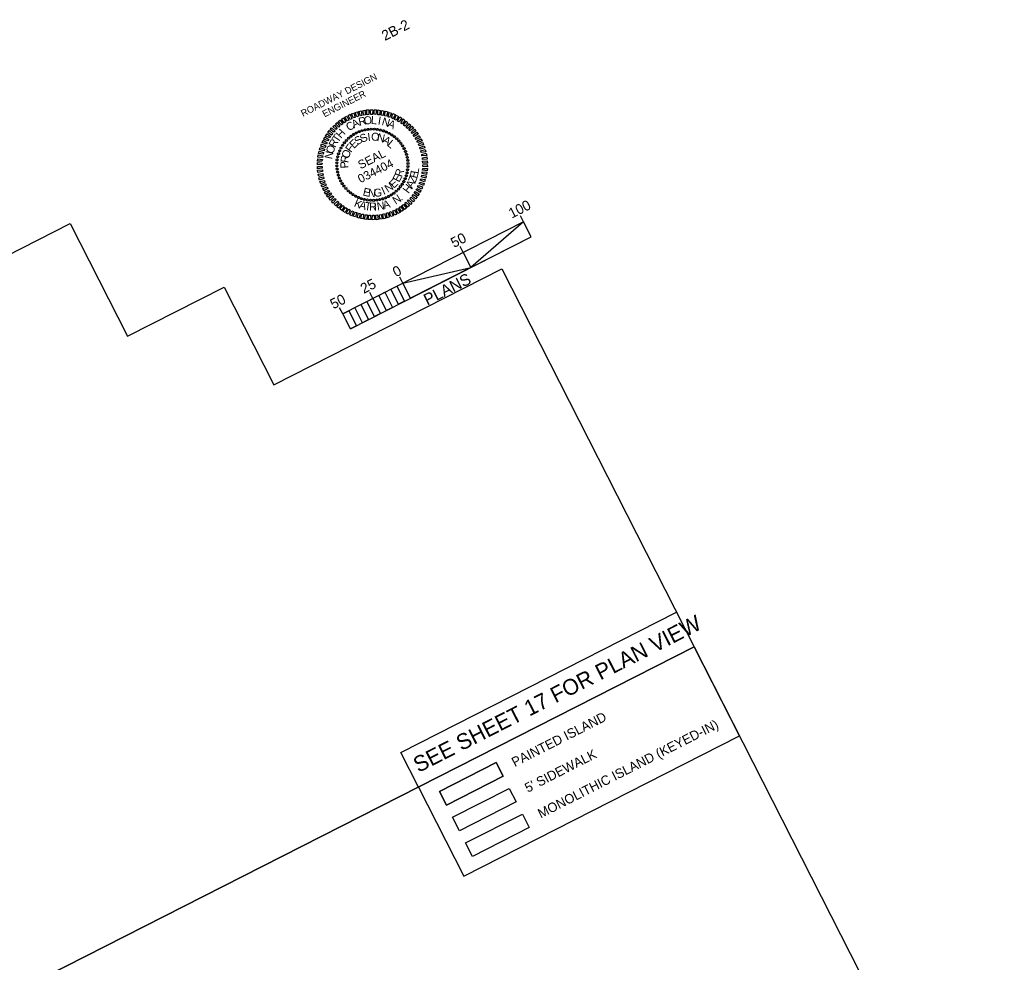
# Model space of a CAD drawing. Extents: x 2331355 to 2333079, y 611262 to 612828.
# Drawn here: x 2332342 to 2333079, y 612132 to 612828 of the extents above; entities that cross this region are included whole.
import ezdxf

# ---------------------------------------------------------------- set-up
doc = ezdxf.new("R2010")
doc.units = 0
for name, color, linetype in [('Default', 7, 'Continuous'), ('Prop Conc 4in Sidewalk', 7, 'Continuous'), ('Prop Conc 5in Monolithic Keyed In Island', 7, 'Continuous'), ('Prop Dimension Text', 7, 'Continuous'), ('Prop Lane Lines', 7, 'Continuous'), ('Sheet Data Field CELL', 7, 'Continuous'), ('Sheet Plan CELL', 7, 'Continuous'), ('Sheet Title CELL', 7, 'Continuous')]:
    doc.layers.add(name, color=color, linetype=linetype)

msp = doc.modelspace()

# ---------------------------------------------------------------- linework, layer by layer
at = {"layer": 'Default'}
msp.add_line((2332379.58, 612677.42), (2332421.89, 612594.18), dxfattribs=at)
for points in [[(2332623.93, 612286.52), (2332827.81, 612390.17), (2332840.79, 612364.62), (2332636.91, 612260.98)], [(2332670.41, 612195.11), (2332874.28, 612298.75), (2332840.79, 612364.62), (2332636.92, 612260.99)]]:
    msp.add_lwpolyline(points, close=True, dxfattribs=at)
at = {"layer": 'Prop Conc 4in Sidewalk'}
msp.add_lwpolyline([(2332662.16, 612238.7), (2332704.1, 612260.02), (2332709.22, 612249.95), (2332667.28, 612228.63)], close=True, dxfattribs=at)
at = {"layer": 'Prop Conc 5in Monolithic Keyed In Island'}
msp.add_lwpolyline([(2332671.81, 612219.72), (2332713.75, 612241.04), (2332718.87, 612230.97), (2332676.93, 612209.65)], close=True, dxfattribs=at)
at = {"layer": 'Prop Lane Lines'}
msp.add_lwpolyline([(2332652.51, 612257.69), (2332694.45, 612279), (2332699.57, 612268.93), (2332657.63, 612247.62)], close=True, dxfattribs=at)
msp.add_lwpolyline([(2332657.63, 612247.62), (2332699.57, 612268.93), (2332694.45, 612279), (2332652.51, 612257.69), (2332657.63, 612247.62)], dxfattribs=at)
at = {"layer": 'Sheet Data Field CELL'}
for p, q in [((2332587.13, 612741.95), (2332587.13, 612741.95)), ((2332588.97, 612743.29), (2332588.97, 612743.29)), ((2332590.99, 612744.42), (2332590.99, 612744.42)), ((2332593.1, 612745.36), (2332593.1, 612745.36)), ((2332595.26, 612746.09), (2332595.26, 612746.09)), ((2332597.43, 612746.71), (2332597.43, 612746.71)), ((2332599.72, 612747.09), (2332599.72, 612747.09)), ((2332602.02, 612747.24), (2332602.02, 612747.24)), ((2332604.32, 612747.27), (2332604.32, 612747.27)), ((2332606.6, 612747), (2332606.6, 612747)), ((2332608.89, 612746.61), (2332608.89, 612746.61)), ((2332611.06, 612745.98), (2332611.06, 612745.98)), ((2332613.26, 612745.19), (2332613.26, 612745.19)), ((2332615.28, 612744.18), (2332615.28, 612744.18)), ((2332617.28, 612742.99), (2332617.28, 612742.99)), ((2332619.17, 612741.67), (2332619.17, 612741.67)), ((2332580.86, 612735.3), (2332580.86, 612735.3)), ((2332582.17, 612737.19), (2332582.17, 612737.19)), ((2332583.63, 612738.91), (2332583.63, 612738.91)), ((2332585.28, 612740.5), (2332585.28, 612740.5)), ((2332620.89, 612740.21), (2332620.89, 612740.21)), ((2332622.48, 612738.56), (2332622.48, 612738.56)), ((2332623.94, 612736.72), (2332623.94, 612736.72)), ((2332625.27, 612734.87), (2332625.27, 612734.87)), ((2332577.23, 612726.9), (2332577.23, 612726.9)), ((2332577.86, 612729.08), (2332577.86, 612729.08)), ((2332578.65, 612731.28), (2332578.65, 612731.28)), ((2332579.66, 612733.3), (2332579.66, 612733.3)), ((2332626.4, 612732.86), (2332626.4, 612732.86)), ((2332627.34, 612730.74), (2332627.34, 612730.74)), ((2332628.08, 612728.58), (2332628.08, 612728.58)), ((2332628.69, 612726.41), (2332628.69, 612726.41)), ((2332576.57, 612722.34), (2332576.57, 612722.34)), ((2332576.6, 612720.04), (2332576.6, 612720.04)), ((2332576.84, 612724.62), (2332576.84, 612724.62)), ((2332629.07, 612724.12), (2332629.07, 612724.12)), ((2332629.22, 612721.82), (2332629.22, 612721.82)), ((2332629.26, 612719.52), (2332629.26, 612719.52)), ((2332576.75, 612717.74), (2332576.75, 612717.74)), ((2332577.13, 612715.45), (2332577.13, 612715.45)), ((2332577.75, 612713.28), (2332577.75, 612713.28)), ((2332627.96, 612712.78), (2332627.96, 612712.78)), ((2332628.59, 612714.95), (2332628.59, 612714.95)), ((2332628.98, 612717.24), (2332628.98, 612717.24)), ((2332578.48, 612711.12), (2332578.48, 612711.12)), ((2332579.42, 612709), (2332579.42, 612709)), ((2332580.55, 612706.99), (2332580.55, 612706.99)), ((2332581.89, 612705.14), (2332581.89, 612705.14)), ((2332623.65, 612704.67), (2332623.65, 612704.67)), ((2332624.97, 612706.56), (2332624.97, 612706.56)), ((2332626.16, 612708.56), (2332626.16, 612708.56)), ((2332627.17, 612710.58), (2332627.17, 612710.58)), ((2332583.34, 612703.3), (2332583.34, 612703.3)), ((2332584.93, 612701.65), (2332584.93, 612701.65)), ((2332586.65, 612700.19), (2332586.65, 612700.19)), ((2332588.54, 612698.87), (2332588.54, 612698.87)), ((2332590.54, 612697.68), (2332590.54, 612697.68)), ((2332614.84, 612697.44), (2332614.84, 612697.44)), ((2332616.85, 612698.57), (2332616.85, 612698.57)), ((2332618.7, 612699.9), (2332618.7, 612699.9)), ((2332620.54, 612701.36), (2332620.54, 612701.36)), ((2332622.19, 612702.95), (2332622.19, 612702.95)), ((2332592.56, 612696.67), (2332592.56, 612696.67)), ((2332594.76, 612695.88), (2332594.76, 612695.88)), ((2332596.94, 612695.25), (2332596.94, 612695.25)), ((2332599.22, 612694.86), (2332599.22, 612694.86)), ((2332601.51, 612694.58), (2332601.51, 612694.58)), ((2332603.8, 612694.62), (2332603.8, 612694.62)), ((2332606.1, 612694.77), (2332606.1, 612694.77)), ((2332608.39, 612695.15), (2332608.39, 612695.15)), ((2332610.56, 612695.77), (2332610.56, 612695.77)), ((2332612.72, 612696.5), (2332612.72, 612696.5)), ((2332670.09, 612656.11), (2332667.83, 612660.56)), ((2332603.24, 612622.11), (2332600.97, 612626.57)), ((2332580.95, 612610.79), (2332578.69, 612615.24))]:
    msp.add_line(p, q, dxfattribs=at)
for points in [[(2332584.32, 612753.29), (2332582.49, 612756.18), (2332584.04, 612756.95), (2332585.45, 612753.84)], [(2332586.57, 612754.43), (2332584.97, 612757.44), (2332586.52, 612758.2), (2332587.7, 612754.97)], [(2332588.96, 612755.52), (2332587.54, 612758.63), (2332589.22, 612759.16), (2332590.17, 612755.92)], [(2332591.38, 612756.33), (2332590.22, 612759.51), (2332591.87, 612760.09), (2332592.57, 612756.78)], [(2332594.01, 612757.07), (2332592.88, 612760.33), (2332594.65, 612760.79), (2332595.11, 612757.35)], [(2332596.56, 612757.65), (2332595.73, 612760.89), (2332597.41, 612761.19), (2332597.7, 612757.84)], [(2332599.09, 612757.92), (2332598.6, 612761.41), (2332600.2, 612761.54), (2332600.32, 612758.16)], [(2332601.64, 612758.15), (2332601.35, 612761.49), (2332603.13, 612761.61), (2332602.93, 612758.18)], [(2332604.34, 612758.21), (2332604.19, 612761.52), (2332605.99, 612761.47), (2332605.51, 612758.12)], [(2332606.81, 612757.92), (2332607, 612761.47), (2332608.72, 612761.13), (2332608.12, 612757.9)], [(2332609.45, 612757.54), (2332609.81, 612760.99), (2332611.55, 612760.61), (2332610.67, 612757.35)], [(2332611.97, 612757.03), (2332612.59, 612760.45), (2332614.29, 612759.93), (2332613.22, 612756.81)], [(2332614.5, 612756.3), (2332615.33, 612759.53), (2332617.04, 612759.01), (2332615.59, 612755.92)], [(2332617, 612755.49), (2332618.03, 612758.71), (2332619.67, 612757.97), (2332618.15, 612754.91)], [(2332619.35, 612754.42), (2332620.59, 612757.57), (2332622.19, 612756.69), (2332620.38, 612753.83)], [(2332621.57, 612753.16), (2332623.09, 612756.22), (2332624.71, 612755.3), (2332622.71, 612752.58)], [(2332576.19, 612746.9), (2332573.65, 612749.11), (2332574.86, 612750.29), (2332576.99, 612747.74)], [(2332578.09, 612748.68), (2332575.57, 612751.09), (2332576.97, 612752.25), (2332578.94, 612749.43)], [(2332580.05, 612750.37), (2332577.73, 612752.95), (2332579.19, 612753.9), (2332581.08, 612751.1)], [(2332582.12, 612751.83), (2332580.04, 612754.53), (2332581.52, 612755.55), (2332583.16, 612752.56)], [(2332623.85, 612751.76), (2332625.59, 612754.76), (2332626.95, 612753.64), (2332624.88, 612751.17)], [(2332625.84, 612750.26), (2332627.84, 612753.1), (2332629.22, 612751.93), (2332626.84, 612749.48)], [(2332627.83, 612748.52), (2332630.02, 612751.23), (2332631.29, 612750.06), (2332628.81, 612747.79)], [(2332629.75, 612746.69), (2332632.15, 612749.33), (2332633.24, 612747.95), (2332630.59, 612745.89)], [(2332569.96, 612738.49), (2332566.99, 612739.94), (2332567.73, 612741.46), (2332570.68, 612739.58)], [(2332571.38, 612740.73), (2332568.34, 612742.32), (2332569.38, 612743.82), (2332571.97, 612741.75)], [(2332572.79, 612742.9), (2332569.93, 612744.71), (2332571.02, 612746.12), (2332573.58, 612743.86)], [(2332574.31, 612744.95), (2332571.68, 612747), (2332572.77, 612748.3), (2332575.32, 612745.85)], [(2332631.49, 612744.76), (2332633.94, 612747.19), (2332635.05, 612745.76), (2332632.28, 612743.93)], [(2332633.08, 612742.76), (2332635.75, 612745), (2332636.73, 612743.5), (2332633.86, 612741.74)], [(2332634.54, 612740.68), (2332637.36, 612742.65), (2332638.29, 612741.12), (2332635.23, 612739.62)], [(2332567.17, 612731.31), (2332563.8, 612731.96), (2332564.4, 612733.64), (2332567.52, 612732.44)], [(2332567.84, 612733.74), (2332564.72, 612734.7), (2332565.24, 612736.4), (2332568.38, 612734.86)], [(2332568.94, 612736.16), (2332565.76, 612737.33), (2332566.5, 612738.97), (2332569.5, 612737.23)], [(2332635.82, 612738.39), (2332638.76, 612740.12), (2332639.59, 612738.55), (2332636.41, 612737.27)], [(2332637, 612736.04), (2332640.06, 612737.55), (2332640.78, 612735.97), (2332637.5, 612734.88)], [(2332637.95, 612733.7), (2332641.06, 612734.99), (2332641.71, 612733.32), (2332638.31, 612732.46)], [(2332566.03, 612726.19), (2332562.69, 612726.44), (2332562.86, 612728.25), (2332566.17, 612727.39)], [(2332566.49, 612728.69), (2332563.12, 612729.22), (2332563.5, 612730.96), (2332566.69, 612729.87)], [(2332638.83, 612731.14), (2332641.9, 612732.29), (2332642.41, 612730.54), (2332638.98, 612729.97)], [(2332639.41, 612728.59), (2332642.6, 612729.51), (2332643.09, 612727.81), (2332639.56, 612727.42)], [(2332639.9, 612726), (2332643.21, 612726.69), (2332643.37, 612724.93), (2332639.9, 612724.76)], [(2332565.57, 612721.01), (2332562.31, 612720.77), (2332562.25, 612722.58), (2332565.66, 612722.19)], [(2332565.77, 612718.39), (2332562.33, 612717.93), (2332562.27, 612719.74), (2332565.7, 612719.66)], [(2332565.62, 612723.6), (2332562.29, 612723.61), (2332562.53, 612725.4), (2332565.92, 612724.82)], [(2332640.05, 612723.47), (2332643.49, 612723.93), (2332643.56, 612722.12), (2332640.13, 612722.2)], [(2332640.25, 612720.84), (2332643.51, 612721.09), (2332643.58, 612719.28), (2332640.17, 612719.67)], [(2332565.93, 612715.86), (2332562.61, 612715.17), (2332562.45, 612716.93), (2332565.92, 612717.1)], [(2332566.41, 612713.27), (2332563.22, 612712.34), (2332562.73, 612714.04), (2332566.27, 612714.44)], [(2332566.99, 612710.72), (2332563.92, 612709.57), (2332563.41, 612711.32), (2332566.85, 612711.89)], [(2332639.34, 612713.17), (2332642.71, 612712.64), (2332642.33, 612710.9), (2332639.13, 612711.99)], [(2332639.79, 612715.67), (2332643.13, 612715.42), (2332642.96, 612713.61), (2332639.66, 612714.47)], [(2332640.2, 612718.26), (2332643.53, 612718.25), (2332643.29, 612716.46), (2332639.9, 612717.03)], [(2332567.87, 612708.16), (2332564.76, 612706.87), (2332564.11, 612708.54), (2332567.52, 612709.4)], [(2332568.82, 612705.81), (2332565.76, 612704.31), (2332565.04, 612705.89), (2332568.33, 612706.97)], [(2332570.01, 612703.47), (2332567.07, 612701.73), (2332566.23, 612703.31), (2332569.42, 612704.58)], [(2332636.89, 612705.7), (2332640.06, 612704.53), (2332639.33, 612702.89), (2332636.33, 612704.63)], [(2332637.98, 612708.12), (2332641.1, 612707.16), (2332640.58, 612705.46), (2332637.44, 612707)], [(2332638.65, 612710.55), (2332642.02, 612709.9), (2332641.43, 612708.22), (2332638.3, 612709.41)], [(2332571.28, 612701.18), (2332568.47, 612699.21), (2332567.54, 612700.74), (2332570.6, 612702.24)], [(2332572.74, 612699.1), (2332570.07, 612696.85), (2332569.1, 612698.36), (2332571.96, 612700.12)], [(2332574.34, 612697.1), (2332571.88, 612694.67), (2332570.77, 612696.1), (2332573.54, 612697.92)], [(2332631.51, 612696.9), (2332634.15, 612694.86), (2332633.05, 612693.56), (2332630.5, 612696.01)], [(2332633.04, 612698.96), (2332635.9, 612697.15), (2332634.81, 612695.74), (2332632.24, 612698)], [(2332634.44, 612701.13), (2332637.48, 612699.54), (2332636.44, 612698.03), (2332633.85, 612700.11)], [(2332635.86, 612703.37), (2332638.83, 612701.92), (2332638.1, 612700.4), (2332635.14, 612702.27)], [(2332576.07, 612695.17), (2332573.67, 612692.53), (2332572.58, 612693.91), (2332575.23, 612695.97)], [(2332577.99, 612693.34), (2332575.81, 612690.63), (2332574.54, 612691.8), (2332577.02, 612694.06)], [(2332579.99, 612691.6), (2332577.99, 612688.76), (2332576.6, 612689.92), (2332578.98, 612692.38)], [(2332581.97, 612690.1), (2332580.23, 612687.1), (2332578.87, 612688.22), (2332580.95, 612690.69)], [(2332623.7, 612690.03), (2332625.78, 612687.33), (2332624.31, 612686.31), (2332622.66, 612689.3)], [(2332625.78, 612691.49), (2332628.09, 612688.91), (2332626.64, 612687.96), (2332624.74, 612690.76)], [(2332627.73, 612693.18), (2332630.25, 612690.77), (2332628.85, 612689.61), (2332626.88, 612692.43)], [(2332629.64, 612694.96), (2332632.18, 612692.74), (2332630.96, 612691.56), (2332628.84, 612694.12)], [(2332584.26, 612688.7), (2332582.73, 612685.64), (2332581.12, 612686.56), (2332583.12, 612689.28)], [(2332586.47, 612687.44), (2332585.23, 612684.29), (2332583.64, 612685.16), (2332585.45, 612688.02)], [(2332588.82, 612686.37), (2332587.79, 612683.15), (2332586.16, 612683.89), (2332587.68, 612686.95)], [(2332591.33, 612685.56), (2332590.49, 612682.33), (2332588.79, 612682.85), (2332590.24, 612685.93)], [(2332593.86, 612684.82), (2332593.23, 612681.41), (2332591.53, 612681.93), (2332592.61, 612685.05)], [(2332596.38, 612684.32), (2332596.02, 612680.86), (2332594.27, 612681.24), (2332595.15, 612684.5)], [(2332599.02, 612683.94), (2332598.82, 612680.39), (2332597.1, 612680.73), (2332597.7, 612683.95)], [(2332601.49, 612683.65), (2332601.64, 612680.34), (2332599.83, 612680.39), (2332600.31, 612683.74)], [(2332604.19, 612683.71), (2332604.48, 612680.36), (2332602.7, 612680.25), (2332602.89, 612683.68)], [(2332606.74, 612683.94), (2332607.22, 612680.45), (2332605.63, 612680.32), (2332605.5, 612683.7)], [(2332609.27, 612684.21), (2332610.1, 612680.97), (2332608.41, 612680.67), (2332608.12, 612684.02)], [(2332611.81, 612684.79), (2332612.95, 612681.53), (2332611.17, 612681.06), (2332610.71, 612684.5)], [(2332614.44, 612685.53), (2332615.6, 612682.35), (2332613.95, 612681.77), (2332613.26, 612685.08)], [(2332616.87, 612686.34), (2332618.28, 612683.23), (2332616.6, 612682.7), (2332615.66, 612685.94)], [(2332619.26, 612687.43), (2332620.86, 612684.42), (2332619.3, 612683.65), (2332618.12, 612686.89)], [(2332621.51, 612688.57), (2332623.34, 612685.68), (2332621.78, 612684.91), (2332620.37, 612688.02)]]:
    msp.add_lwpolyline(points, close=True, dxfattribs=at)
for centre, major_axis in [((2332585.32, 612740.5), (-0.505, 0.562)), ((2332587.09, 612741.96), (-0.454, 0.604)), ((2332588.99, 612743.26), (-0.4, 0.641)), ((2332590.99, 612744.39), (-0.342, 0.673)), ((2332593.08, 612745.34), (-0.282, 0.701)), ((2332595.24, 612746.1), (-0.22, 0.723)), ((2332597.46, 612746.68), (-0.156, 0.739)), ((2332599.73, 612747.05), (-0.091, 0.75)), ((2332602.02, 612747.23), (-0.026, 0.755)), ((2332604.31, 612747.21), (0.04, 0.754)), ((2332606.6, 612746.99), (0.106, 0.748)), ((2332608.86, 612746.57), (0.171, 0.736)), ((2332611.07, 612745.95), (0.234, 0.718)), ((2332613.22, 612745.14), (0.296, 0.695)), ((2332615.29, 612744.15), (0.355, 0.667)), ((2332617.27, 612742.99), (0.412, 0.633)), ((2332619.13, 612741.65), (0.466, 0.595)), ((2332579.69, 612733.31), (-0.667, 0.355)), ((2332580.85, 612735.28), (-0.633, 0.412)), ((2332582.19, 612737.15), (-0.595, 0.466)), ((2332583.68, 612738.89), (-0.552, 0.516)), ((2332620.88, 612740.16), (0.516, 0.552)), ((2332622.49, 612738.52), (0.562, 0.505)), ((2332623.94, 612736.75), (0.604, 0.454)), ((2332625.24, 612734.85), (0.641, 0.4)), ((2332626.37, 612732.85), (0.673, 0.342)), ((2332577.27, 612726.87), (-0.736, 0.171)), ((2332577.89, 612729.08), (-0.718, 0.234)), ((2332578.7, 612731.23), (-0.695, 0.296)), ((2332627.32, 612730.76), (0.701, 0.282)), ((2332628.09, 612728.6), (0.723, 0.22)), ((2332628.66, 612726.38), (0.739, 0.156)), ((2332576.61, 612720.03), (-0.755, -0.026)), ((2332576.63, 612722.33), (-0.754, 0.04)), ((2332576.85, 612724.62), (-0.748, 0.106)), ((2332629.04, 612724.11), (0.75, 0.091)), ((2332629.19, 612719.53), (0.754, -0.04)), ((2332629.21, 612721.82), (0.755, 0.026)), ((2332576.79, 612717.75), (-0.75, -0.091)), ((2332577.17, 612715.48), (-0.739, -0.156)), ((2332577.74, 612713.26), (-0.723, -0.22)), ((2332578.5, 612711.09), (-0.701, -0.282)), ((2332627.93, 612712.77), (0.718, -0.234)), ((2332628.55, 612714.99), (0.736, -0.171)), ((2332628.97, 612717.24), (0.748, -0.106)), ((2332579.45, 612709), (-0.673, -0.342)), ((2332580.58, 612707), (-0.641, -0.4)), ((2332581.88, 612705.11), (-0.604, -0.454)), ((2332623.63, 612704.71), (0.595, -0.466)), ((2332624.97, 612706.58), (0.633, -0.412)), ((2332626.14, 612708.55), (0.667, -0.355)), ((2332627.13, 612710.62), (0.695, -0.296)), ((2332583.34, 612703.34), (-0.562, -0.505)), ((2332584.95, 612701.7), (-0.516, -0.552)), ((2332586.69, 612700.21), (-0.466, -0.595)), ((2332588.56, 612698.87), (-0.412, -0.633)), ((2332590.54, 612697.7), (-0.355, -0.667)), ((2332592.61, 612696.71), (-0.296, -0.695)), ((2332612.75, 612696.52), (0.282, -0.701)), ((2332614.84, 612697.47), (0.342, -0.673)), ((2332616.84, 612698.6), (0.4, -0.641)), ((2332618.73, 612699.9), (0.454, -0.604)), ((2332620.5, 612701.36), (0.505, -0.562)), ((2332622.14, 612702.96), (0.552, -0.516)), ((2332594.76, 612695.91), (-0.234, -0.718)), ((2332596.97, 612695.29), (-0.171, -0.736)), ((2332599.23, 612694.87), (-0.106, -0.748)), ((2332601.51, 612694.65), (-0.04, -0.754)), ((2332603.81, 612694.63), (0.026, -0.755)), ((2332606.09, 612694.81), (0.091, -0.75)), ((2332608.36, 612695.18), (0.156, -0.739)), ((2332610.58, 612695.76), (0.22, -0.723))]:
    msp.add_ellipse(centre, major_axis=major_axis, ratio=0.999708, dxfattribs=at)
at = {"layer": 'Sheet Plan CELL'}
for points in [[(2331354.84, 612198.14), (2332231.99, 612644.09), (2332248.84, 612610.95), (2332379.58, 612677.42), (2332421.89, 612594.18), (2332493.28, 612630.48), (2332529.96, 612558.33), (2332698.67, 612644.11), (2332840.79, 612364.62), (2331592.76, 611730.15)], [(2331592.76, 611730.15), (2332840.78, 612364.62), (2333078.69, 611896.65), (2331830.66, 611262.19)]]:
    msp.add_lwpolyline(points, close=True, dxfattribs=at)
at = {"layer": 'Sheet Title CELL'}
for p, q in [((2332714.65, 612678.76), (2332712.39, 612683.22)), ((2332714.65, 612678.76), (2332580.94, 612610.77)), ((2332586.61, 612599.63), (2332720.32, 612667.61)), ((2332670.08, 612656.1), (2332667.82, 612660.54)), ((2332670.08, 612656.1), (2332675.75, 612644.95)), ((2332625.52, 612633.42), (2332623.25, 612637.88)), ((2332603.23, 612622.09), (2332600.96, 612626.56)), ((2332612.14, 612626.64), (2332617.81, 612615.49)), ((2332580.94, 612610.77), (2332578.68, 612615.22)), ((2332578.68, 612615.22), (2332578.68, 612615.22))]:
    msp.add_line(p, q, dxfattribs=at)
for points in [[(2332714.65, 612678.76), (2332675.75, 612644.95), (2332720.32, 612667.61)], [(2332625.52, 612633.42), (2332675.75, 612644.95), (2332631.18, 612622.28)], [(2332616.6, 612628.9), (2332621.06, 612631.17), (2332626.73, 612620.02), (2332622.27, 612617.76)], [(2332607.69, 612624.36), (2332612.14, 612626.64), (2332617.81, 612615.49), (2332613.35, 612613.23)], [(2332589.86, 612615.31), (2332594.32, 612617.56), (2332599.99, 612606.42), (2332595.54, 612604.16)], [(2332598.78, 612619.83), (2332603.23, 612622.09), (2332608.89, 612610.96), (2332604.44, 612608.7)], [(2332580.94, 612610.77), (2332585.4, 612613.04), (2332591.07, 612601.9), (2332586.61, 612599.63)]]:
    msp.add_lwpolyline(points, close=True, dxfattribs=at)

# ---------------------------------------------------------------- texts
at = {"layer": 'Default'}
msp.add_text('SEE SHEET 17 FOR PLAN VIEW', height=11.6664, rotation=26.94752, dxfattribs=at).set_placement((2332636.97, 612271.34))
at = {"layer": 'Prop Dimension Text'}
for s, p in [('PAINTED ISLAND', (2332708.1, 612275.68)), ('MONOLITHIC ISLAND (KEYED-IN)', (2332727.4, 612237.71)), ("5' SIDEWALK", (2332717.75, 612256.7))]:
    msp.add_text(s, height=7, rotation=26.94653, dxfattribs=at).set_placement(p)
at = {"layer": 'Sheet Data Field CELL'}
for s, height, rotation, p in [('2B-2', 7.5, 26.94944, (2332612.19, 612812.36)), ('R', 5.92, 12.56828, (2332593.28, 612749.61)), ('O', 5.92, 5.36834, (2332596.75, 612750.56)), ('L', 5.92, 358.16806, (2332601.74, 612751.01)), ('I', 5.92, 350.96732, (2332606.67, 612750.78)), ('N', 5.92, 343.76609, (2332609.43, 612750.4)), ('C', 5.92, 34.16705, (2332585.77, 612745.51)), ('A', 5.92, 26.9675, (2332589.29, 612747.73)), ('A', 5.92, 336.56433, (2332613.61, 612749.12)), ('T', 5.92, 55.76695, (2332577.51, 612736.79)), ('H', 5.92, 48.56666, (2332579.71, 612739.92)), ('S', 5.92, 35.20279, (2332592.03, 612735.17)), ('S', 5.92, 25.84758, (2332595.34, 612736.99)), ('I', 5.92, 7.13678, (2332599.67, 612738.45)), ('O', 5.92, 357.78066, (2332601.87, 612738.79)), ('N', 5.92, 348.42379, (2332605.96, 612738.58)), ('A', 5.92, 329.70745, (2332609.88, 612737.57)), ('O', 5.92, 70.16892, (2332573.77, 612728.51)), ('R', 5.92, 62.96769, (2332575.44, 612733.08)), ('F', 5.91, 53.91421, (2332587.12, 612729.54)), ('E', 5.92, 44.55825, (2332589.35, 612732.5)), ('L', 5.92, 320.34803, (2332613.38, 612735.33)), ('N', 5.92, 77.37068, (2332573.06, 612724.69)), ('R', 5.92, 81.98683, (2332585.09, 612722.05)), ('O', 5.92, 72.62842, (2332585.51, 612725.18)), ('SEAL', 6.294, 26.94718, (2332594.22, 612717.5)), ('P', 5.92, 91.34607, (2332585.18, 612718.29)), ('034404', 6.296, 26.94718, (2332594.11, 612707.19)), ('E', 5.92, 61.07127, (2332622.58, 612707.49)), ('R', 5.92, 70.42859, (2332624.71, 612711.41)), ('Z', 5.92, 68.53198, (2332634.51, 612706.79)), ('E', 5.92, 75.07146, (2332635.95, 612710.42)), ('L', 5.92, 81.24624, (2332636.92, 612713.97)), ('I', 5.92, 23.64838, (2332611.15, 612698.57)), ('N', 5.92, 33.00357, (2332614.33, 612700.08)), ('E', 5.92, 42.35894, (2332618.62, 612703.07)), ('H', 5.92, 53.32232, (2332629.64, 612699.15)), ('A', 5.92, 61.28226, (2332632.44, 612702.99)), ('E', 5.92, 346.22407, (2332595.41, 612698.36)), ('N', 5.92, 355.58114, (2332599.51, 612697.33)), ('G', 5.92, 4.93742, (2332604.14, 612697.11)), ('N', 5.92, 32.54255, (2332620.11, 612691.3)), ('K', 5.92, 338.11517, (2332588.83, 612690.28)), ('A', 5.92, 345.01937, (2332592.65, 612688.74)), ('T', 5.92, 352.26908, (2332596.84, 612687.64)), ('R', 5.92, 358.25191, (2332600.37, 612687.13)), ('I', 5.92, 4.65703, (2332604.19, 612686.99)), ('N', 5.92, 8.7779, (2332606.65, 612687.13)), ('A', 5.92, 17.19853, (2332611.61, 612687.97)), ('.', 5.92, 40.96318, (2332624.31, 612694.06)), ('100', 7.5, 26.9513, (2332705.92, 612681.06)), ('50', 7.5, 26.9513, (2332663.2, 612659.33)), ('25', 7.5, 26.9513, (2332596.48, 612625.41)), ('50', 7.5, 26.9513, (2332574.06, 612614.01))]:
    msp.add_text(s, height=height, rotation=rotation, dxfattribs=at).set_placement(p)
at = {"layer": 'Sheet Plan CELL'}
for s, height, p in [('ROADWAY DESIGN', 5.0001, (2332551.62, 612756.27)), ('ENGINEER', 5, (2332567.5, 612755.89))]:
    msp.add_text(s, height=height, rotation=26.94653, dxfattribs=at).set_placement(p)
at = {"layer": 'Sheet Title CELL'}
for s, height, p in [('0', 7.5, (2332620.28, 612637.66)), ('PLANS', 8.5, (2332643.52, 612616.77))]:
    msp.add_text(s, height=height, rotation=26.9513, dxfattribs=at).set_placement(p)

doc.saveas('drawing.dxf')
